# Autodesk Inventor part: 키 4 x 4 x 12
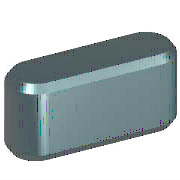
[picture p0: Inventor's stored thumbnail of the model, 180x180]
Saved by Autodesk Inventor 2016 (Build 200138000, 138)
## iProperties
IsCustomPart: 1
Created: 2012-02
Part Number: 키 4 x 4 x 12
Material: 강철, 연강
Description: 키 및 해당 키홈
Document SubType Name: Modeling
Standard: KS B 1311
Designer: mduedu
Standards Organization: KS
Language: ko-KR
Size Designation: 4 x 4 x 12
Categories: <MemberInstance><Categories><Category DisplayName="샤프트 부품" InternalName="7f7aeb1f-a693-4053-b835-cee3144e0d98" Mnemonic="SHFT"><Category DisplayName="키" Interna
Density: 1 g/cm^3
Appearance: 강철
Author: mduedu
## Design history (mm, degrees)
workplane "Work Plane1"
workplane "Work Plane2"
sketch "스케치1"
  geometry: L1 (2, 2)-(10, 2); L2 (10, -2)-(2, -2); L3 (0, 9.4)-(0, -7.4) reference; L4 (-5, 0)-(30, 0) reference; L5 (12, 0)-(12, 7); A1 r 2 centre (2, 0) between (2, 2) and (2, -2); A2 r 2 centre (10, 0) between (10, -2) and (10, 2)
  constraints: 6 end point, 5 point on circle, 4 tangent, 3 point on line, 2 centre point, 1 horizontal, 1 parallel, 1 perpendicular
  dimensions: "d0" = 2 radius of A1 (= 0.5 x PB); "d13" = 2 radius of A2 (= 0.5 x PB); "d14" = 12 distance between parallel lines of L5 L3 (= NLG)
extrude "본체1" new body sketch "스케치1" taper "d3" = 0 deg; stored distance "d4" = 10
workplane "Work Plane3"
body "Solid1"
chamfer "모따기1" distance "d8" = 0.25 (= PHH); stored, may be unused: second distance "d9" = 0.25 (= PHH), angle "d15" = 45 deg
other parameters: "d1" = -2.5 (= -PNT), "d2" = 1.5 (= PH - PNT), "NLG" = 12 [user parameter; used in 3 equation terms], "PB" = 4 [user parameter; used in 2 equation terms], "PNT" = 2.5 [user parameter; used in 2 equation terms], "PH" = 4 [user parameter; used in 1 equation term], "PHH" = 0.25 [user parameter; used in 2 equation terms], "d10" = 0, "d16" = 0, "d17" = 0, "d18" = 0, "PLB2" = 12 (= NLG) [user parameter], "WDMAX" = 12 [user parameter], "PLB1" = 12 (= NLG) [user parameter], "RR" = 0.08 [user parameter], "PUEB" = 1.8 [user parameter]
